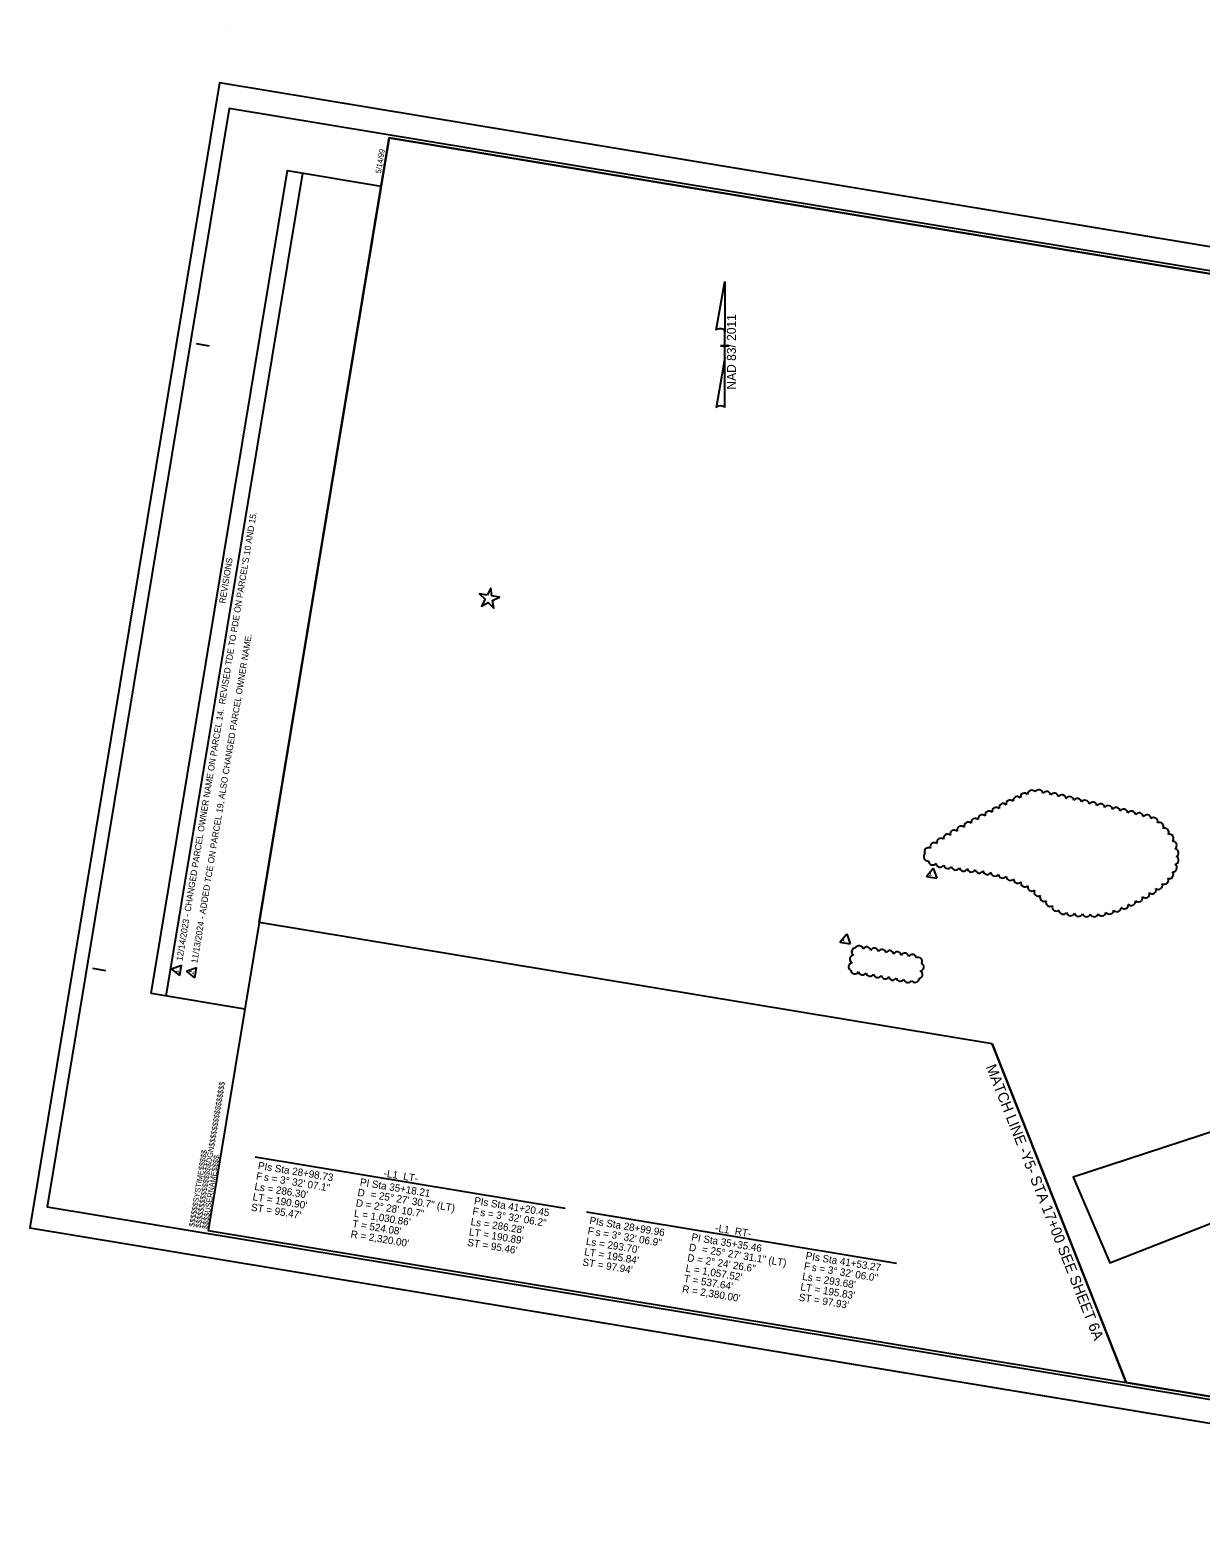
# Model space of a CAD drawing. Extents: x 2191522 to 2193565, y 85992 to 87403.
# Drawn here: x 2191522 to 2192631, y 85992 to 87403 of the extents above; entities that cross this region are included whole.
import ezdxf

# ---------------------------------------------------------------- set-up
doc = ezdxf.new("R2010")
doc.units = 0
for name, color, linetype in [('Exist Roads EOP', 7, 'Continuous'), ('Exist Structure Minor Footbridge', 7, 'Continuous'), ('Model Boundary Lines', 7, 'Continuous'), ('Model Boundary Lines Text', 7, 'Continuous'), ('Old_Level_2', 7, 'Continuous'), ('Scratch_Level_0', 7, 'Continuous'), ('Sheet Border Standard 30in CELL', 7, 'Continuous'), ('Sheet Cutting Line CELL', 7, 'Continuous'), ('Sheet Plot Border Inside CELL', 7, 'Continuous'), ('Sheet Plot Border Outside CELL', 7, 'Continuous')]:
    doc.layers.add(name, color=color, linetype=linetype)

msp = doc.modelspace()

# ---------------------------------------------------------------- linework, layer by layer
at = {"layer": 'Exist Roads EOP'}
for p, q in [((2191651.6, 86487.2), (2191780.9, 87267.2)), ((2192371.8, 86600.5), (2192378.1, 86608.4)), ((2192378.1, 86608.4), (2192381.6, 86598.9)), ((2192371.8, 86600.5), (2192381.6, 86598.9)), ((2192289.7, 86538.3), (2192296.1, 86546.2)), ((2192289.7, 86538.3), (2192299.5, 86536.7)), ((2192296.1, 86546.2), (2192299.5, 86536.7)), ((2191656.5, 86513.1), (2191666, 86516.6)), ((2191664.4, 86506.8), (2191656.5, 86513.1)), ((2191664.4, 86506.8), (2191666, 86516.6)), ((2191670.6, 86510.8), (2191680.1, 86514.3)), ((2191678.5, 86504.5), (2191670.6, 86510.8)), ((2191678.5, 86504.5), (2191680.1, 86514.3))]:
    msp.add_line(p, q, dxfattribs=at)
msp.add_lwpolyline([(2191637.3, 86489.6), (2191766.5, 87269.6), (2191855.1, 87254.9), (2191725.9, 86474.9)], close=True, dxfattribs=at)
for centre, radius, start, end in [((2192464.5, 86675.6), 3.94, 42.184, 187.184), ((2192471.3, 86678.4), 3.94, 37.1203, 182.1203), ((2192477.9, 86678.9), 3.94, 6.4213, 151.4213), ((2192485.3, 86677.3), 3.94, 4.7516, 149.7516), ((2192492.6, 86675.7), 3.94, 4.5876, 149.5876), ((2192499.9, 86674), 3.94, 4.5037, 149.5037), ((2192437.7, 86662.2), 3.94, 45.0572, 190.0572), ((2192444.3, 86665.7), 3.94, 44.7241, 189.7241), ((2192451, 86669.1), 3.94, 44.2581, 189.2581), ((2192457.7, 86672.4), 3.94, 43.5376, 188.5376), ((2192507.2, 86672.3), 3.94, 4.4503, 149.4503), ((2192514.5, 86670.6), 3.94, 4.4124, 149.4124), ((2192521.8, 86668.9), 3.94, 4.3838, 149.3838), ((2192529.2, 86667.2), 3.94, 4.3612, 149.3612), ((2192536.5, 86665.5), 3.94, 4.3514, 149.3514), ((2192543.8, 86663.8), 3.94, 4.3514, 149.3514), ((2192551.1, 86662.1), 3.94, 4.3514, 149.3514), ((2192558.4, 86660.4), 3.94, 4.3514, 149.3514), ((2192411.2, 86648.1), 3.94, 46.3521, 191.3521), ((2192417.8, 86651.7), 3.94, 45.8668, 190.8668), ((2192424.4, 86655.2), 3.94, 45.519, 190.519), ((2192431, 86658.7), 3.94, 45.3108, 190.3108), ((2192565.7, 86658.6), 3.94, 4.3514, 149.3514), ((2192573.1, 86656.9), 3.94, 4.3514, 149.3514), ((2192580.4, 86655.2), 3.94, 4.3514, 149.3514), ((2192586.8, 86652.5), 3.94, 344.3792, 129.3792), ((2192592.4, 86647.9), 3.94, 332.5229, 117.5229), ((2192385.4, 86632.9), 3.94, 50.5072, 195.5072), ((2192391.7, 86636.8), 3.94, 48.8492, 193.8492), ((2192398.1, 86640.7), 3.94, 47.7533, 192.7533), ((2192404.6, 86644.4), 3.94, 46.9602, 191.9602), ((2192597.4, 86642.5), 3.94, 327.8467, 112.8467), ((2192601.7, 86636.6), 3.94, 318.449, 103.449), ((2192372.9, 86619.4), 3.94, 135.4839, 280.4839), ((2192373.6, 86623.9), 3.94, 61.669, 206.669), ((2192379.2, 86628.6), 3.94, 53.4684, 198.4684), ((2192604.8, 86630), 3.94, 308.1648, 93.1648), ((2192606.6, 86623), 3.94, 294.9528, 79.9528), ((2192377.6, 86615.4), 3.94, 178.1556, 323.1556), ((2192384.6, 86613.3), 3.94, 184.4334, 329.4334), ((2192391.9, 86611.9), 3.94, 187.3592, 332.3592), ((2192399.3, 86610.6), 3.94, 189.1365, 334.1365), ((2192406.7, 86609.6), 3.94, 190.3607, 335.3607), ((2192414.2, 86608.7), 3.94, 190.4949, 335.4949), ((2192604.9, 86608.9), 3.94, 267.7815, 52.7815), ((2192606.6, 86615.9), 3.94, 280.1316, 65.1316), ((2192421.7, 86607.7), 3.94, 188.8315, 333.8315), ((2192429.1, 86606.4), 3.94, 186.8467, 331.8467), ((2192436.5, 86604.9), 3.94, 184.5107, 329.5107), ((2192443.8, 86603), 3.94, 181.722, 326.722), ((2192451.1, 86600.7), 3.94, 178.3408, 323.3408), ((2192458.1, 86598), 3.94, 174.1741, 319.1741), ((2192465, 86594.6), 3.94, 168.9629, 313.9629), ((2192591.3, 86592.3), 3.94, 234.6256, 19.6256), ((2192596.9, 86597.1), 3.94, 240.9529, 25.9529), ((2192601.6, 86602.5), 3.94, 252.7106, 37.7106), ((2192471.5, 86590.6), 3.94, 162.3858, 307.3858), ((2192477.5, 86585.9), 3.94, 155.7293, 300.7293), ((2192483.1, 86580.9), 3.94, 156.1791, 301.1791), ((2192572.4, 86580.4), 3.94, 225.8288, 10.8288), ((2192578.9, 86584.1), 3.94, 227.8967, 12.8967), ((2192585.2, 86588), 3.94, 230.6533, 15.6533), ((2192488.8, 86576.1), 3.94, 158.5484, 303.5484), ((2192494.7, 86571.7), 3.94, 163.4577, 308.4577), ((2192501.1, 86568.7), 3.94, 180.9521, 325.9521), ((2192508.2, 86567.3), 3.94, 192.2119, 337.2119), ((2192515.7, 86566.7), 3.94, 193.727, 338.727), ((2192523.2, 86566.3), 3.94, 194.5399, 339.5399), ((2192530.5, 86566.3), 3.94, 200.4618, 345.4618), ((2192537.8, 86567.1), 3.94, 207.9418, 352.9418), ((2192545, 86568.8), 3.94, 213.4956, 358.4956), ((2192552.1, 86571.1), 3.94, 217.7221, 2.7221), ((2192559, 86573.9), 3.94, 221.0291, 6.0291), ((2192565.7, 86577), 3.94, 223.6842, 8.6842), ((2192302.9, 86522.2), 3.82, 98.0917, 243.0917), ((2192304.6, 86529.1), 3.82, 90.4337, 235.4337), ((2192307.9, 86531.2), 3.82, 8.0917, 153.0917), ((2192315.1, 86530), 3.82, 8.0917, 153.0917), ((2192322.3, 86528.8), 3.82, 8.0917, 153.0917), ((2192329.5, 86527.7), 3.82, 8.0917, 153.0917), ((2192336.7, 86526.5), 3.82, 8.0917, 153.0917), ((2192343.9, 86525.3), 3.82, 8.0917, 153.0917), ((2192351.1, 86524.1), 3.82, 8.0917, 153.0917), ((2192358.3, 86522.9), 3.82, 8.0917, 153.0917), ((2192363.7, 86520), 3.82, 330.5198, 115.5198), ((2192301.7, 86515), 3.82, 98.0917, 243.0917), ((2192303.8, 86512.1), 3.82, 188.0917, 333.0917), ((2192311, 86511), 3.82, 188.0917, 333.0917), ((2192318.2, 86509.8), 3.82, 188.0917, 333.0917), ((2192364.1, 86507.5), 3.82, 278.0917, 63.0917), ((2192365.3, 86514.7), 3.82, 278.0917, 63.0917), ((2192325.4, 86508.6), 3.82, 188.0917, 333.0917), ((2192332.6, 86507.4), 3.82, 188.0917, 333.0917), ((2192339.7, 86506.2), 3.82, 188.0917, 333.0917), ((2192346.9, 86505), 3.82, 188.0917, 333.0917), ((2192354.1, 86503.8), 3.82, 188.0917, 333.0917), ((2192360.8, 86504), 3.82, 210.4855, 355.4855)]:
    msp.add_arc(centre, radius, start, end, dxfattribs=at)
at = {"layer": 'Exist Structure Minor Footbridge'}
msp.add_lwpolyline([(2191955.5, 86867.3), (2191948.4, 86868.5), (2191953.5, 86863.3), (2191950.1, 86856.8), (2191956.6, 86860.1), (2191961.7, 86854.9), (2191960.6, 86862.1), (2191967.1, 86865.4), (2191960, 86866.5), (2191958.9, 86873.7), (2191955.5, 86867.3)], dxfattribs=at)
at = {"layer": 'Model Boundary Lines'}
for p, q in [((2192172.4, 87118.3), (2192180.6, 87164.6)), ((2192180.6, 87164.6), (2192180.6, 87164.6)), ((2192180.6, 87164.6), (2192180.6, 87164.6)), ((2192180.6, 87164.6), (2192180.6, 87116.8)), ((2192180.6, 87092), (2192180.6, 87118.2)), ((2192180.6, 87116.8), (2192180.6, 87118.2)), ((2192180.2, 87103.6), (2192176.6, 87103.6)), ((2192176.6, 87103.6), (2192176.6, 87103.6)), ((2192176.7, 87103.6), (2192184.7, 87103.6)), ((2192180.6, 87092), (2192172.3, 87044.8)), ((2192180.7, 87045), (2192180.6, 87092))]:
    msp.add_line(p, q, dxfattribs=at)
for centre, start_param, end_param in [((2192176.5, 87117.8), 0.216388, 2.908219), ((2192176.5, 87044.6), 0.201328, 3.141593)]:
    msp.add_ellipse(centre, major_axis=(4.23, -0.03), ratio=0.461098, start_param=start_param, end_param=end_param, dxfattribs=at)
at = {"layer": 'Model Boundary Lines Text'}
for p, q in [((2191735.6, 86334.8), (2192029.3, 86286.1)), ((2192049.7, 86282.7), (2192343.3, 86234.1))]:
    msp.add_line(p, q, dxfattribs=at)
at = {"layer": 'Old_Level_2'}
msp.add_lwpolyline([(2192434, 86441.8), (2191739.5, 86556.9), (2191853, 87242.1), (2191862.7, 87300.8), (2193012.6, 87110.3), (2193009.4, 87091.1), (2192997.5, 87019.1), (2193130.1, 86997.1), (2193116.8, 86917.1), (2193222.5, 86899.6), (2193235.6, 86410.4), (2193213.8, 86278.1), (2193023.9, 86309.5), (2192994.1, 86129.4), (2192901.4, 86144.8), (2192889.2, 86066.4), (2192560.7, 86120.9), (2192457.9, 86381.3)], close=True, dxfattribs=at)
msp.add_lwpolyline([(2192752, 86394.5), (2192510.7, 86315.5), (2192510.7, 86315.5), (2192545.4, 86234.5), (2192545.4, 86234.5), (2192721.3, 86303.1)], dxfattribs=at)
at = {"layer": 'Scratch_Level_0'}
for p, q in [((2191710.4, 87403.1), (2191710.4, 87403.1)), ((2192434, 86441.8), (2191739.5, 86556.9)), ((2192434, 86441.8), (2192560.7, 86120.9))]:
    msp.add_line(p, q, dxfattribs=at)
at = {"layer": 'Sheet Border Standard 30in CELL'}
for p, q in [((2191863.7, 87300.7), (2191863.7, 87300.7)), ((2191679.9, 87105.6), (2191692.2, 87103.6)), ((2191581.8, 86513.7), (2191594.1, 86511.6))]:
    msp.add_line(p, q, dxfattribs=at)
msp.add_lwpolyline([(2193342.6, 87055.6), (2191862.7, 87300.8), (2191691.1, 86265), (2193170.9, 86019.8)], close=True, dxfattribs=at)
at = {"layer": 'Sheet Cutting Line CELL'}
for p, q in [((2191702.1, 87352.8), (2191522.3, 86267.6)), ((2193363.4, 87077.5), (2191702.1, 87352.8)), ((2191522.3, 86267.6), (2193183.6, 85992.3))]:
    msp.add_line(p, q, dxfattribs=at)
at = {"layer": 'Sheet Plot Border Inside CELL'}
msp.add_lwpolyline([(2193355.3, 87056.1), (2191711.2, 87328.5), (2191538.7, 86287.6), (2193182.8, 86015.2)], close=True, dxfattribs=at)
at = {"layer": 'Sheet Plot Border Outside CELL'}
msp.add_lwpolyline([(2193363.4, 87077.5), (2191702.1, 87352.8), (2191522.3, 86267.6), (2193183.6, 85992.3)], close=True, dxfattribs=at)

# ---------------------------------------------------------------- texts
at = {"layer": 'Exist Roads EOP'}
for s, height, rotation, p in [("  12/14/2023 - CHANGED PARCEL OWNER NAME ON PARCEL 14.  REVISED TDE TO PDE ON PARCEL'S 10 AND 15.", 6, 80.5917, (2191666.1, 86515.8)), ('REVISIONS', 6, 80.5917, (2191707.4, 86859)), ('  11/13/2024 - ADDED TCE ON PARCEL 19, ALSO CHANGED PARCEL OWNER NAME.', 6, 80.5917, (2191680.2, 86513.5)), (' 1', 4.5, 350.5917, (2192371.6, 86601.9)), (' 1', 4.5, 350.5917, (2192289.6, 86539.7)), (' 1', 4.5, 80.5917, (2191663, 86506.6)), ('2', 4.5, 80.5917, (2191677.5, 86507.4))]:
    msp.add_text(s, height=height, rotation=rotation, dxfattribs=at).set_placement(p)
at = {"layer": 'Model Boundary Lines'}
msp.add_text('NAD 83/ 2011', height=8.5, rotation=90, dxfattribs=at).set_placement((2192191.1, 87062.1))
at = {"layer": 'Model Boundary Lines Text'}
for s, rotation, p in [('PIs Sta 28+98.73', 350.5917, (2191738, 86323.4)), ('F', 350.5917, (2191736.3, 86313.5)), ('s = 3%%d 32\' 07.1"', 350.5917, (2191743.7, 86312.3)), ('PI Sta 35+18.21', 350.5917, (2191834.6, 86307.7)), ('-L1_LT-', 350.5915, (2191857.1, 86316.2)), ("LT = 190.90'", 350.5917, (2191733, 86293.8)), ("Ls = 286.30'", 350.5917, (2191734.7, 86303.6)), ('D', 350.5917, (2191832.3, 86297.9)), ('= 25%%d 27\' 30.7" (LT)', 350.5917, (2191844.6, 86296)), ('PIs Sta 41+20.45', 350.5917, (2191942.8, 86290.1)), ("ST = 95.47'", 350.5917, (2191731.4, 86283.9)), ("L = 1,030.86'", 350.5917, (2191829, 86278.2)), ('D = 2%%d 28\' 10.7"', 350.5917, (2191830.7, 86288)), ('F', 350.5917, (2191941.2, 86280.2)), ('s = 3%%d 32\' 06.2"', 350.5917, (2191948.6, 86279)), ("T = 524.08'", 350.5917, (2191827.4, 86268.3)), ("Ls = 286.28'", 350.5917, (2191939.5, 86270.3)), ('PIs Sta 28+99.96', 350.5917, (2192052, 86271.3)), ('-L1_RT-', 350.5915, (2192171.2, 86264.2)), ("R = 2,320.00'", 350.5917, (2191825.8, 86258.4)), ("ST = 95.46'", 350.5917, (2191936.3, 86250.6)), ("LT = 190.89'", 350.5917, (2191937.9, 86260.5)), ("Ls = 293.70'", 350.5917, (2192048.7, 86251.6)), ('F', 350.5917, (2192050.3, 86261.5)), ('s = 3%%d 32\' 06.9"', 350.5917, (2192057.8, 86260.2)), ('PI Sta 35+35.46', 350.5917, (2192148.6, 86255.6)), ("LT = 195.84'", 350.5917, (2192047.1, 86241.7)), ('D = 2%%d 24\' 26.6"', 350.5917, (2192144.7, 86236)), ('D', 350.5917, (2192146.3, 86245.9)), ('= 25%%d 27\' 31.1" (LT)', 350.5917, (2192158.6, 86244)), ('PIs Sta 41+53.27', 350.5917, (2192256.8, 86238)), ("ST = 97.94'", 350.5917, (2192045.4, 86231.9)), ("L = 1,057.52'", 350.5917, (2192143.1, 86226.1)), ('F', 350.5917, (2192255.2, 86228.2)), ('s = 3%%d 32\' 06.0"', 350.5917, (2192262.6, 86226.9)), ("R = 2,380.00'", 350.5917, (2192139.8, 86206.4)), ("T = 537.64'", 350.5917, (2192141.4, 86216.3)), ("LT = 195.83'", 350.5917, (2192251.9, 86208.4)), ("Ls = 293.68'", 350.5917, (2192253.6, 86218.3)), ("ST = 97.93'", 350.5917, (2192250.3, 86198.6))]:
    msp.add_text(s, height=7, rotation=rotation, dxfattribs=at).set_placement(p)
at = {"layer": 'Scratch_Level_0'}
msp.add_text('MATCH LINE -Y5- STA 17+00 SEE SHEET 6A', height=10, rotation=291.5478, dxfattribs=at).set_placement((2192427.8, 86420.2))
at = {"layer": 'Sheet Border Standard 30in CELL'}
for s, p in [('5/14/99', (2191854.8, 87266.5)), ('$$$$$$$$$$$$$$$$DGN$$$$$$$$$$$$$$$$', (2191684.2, 86267)), ('$$$$$$SYSTIME$$$$$', (2191678.2, 86268.2)), ('$$$$USERNAME$$$$', (2191690.4, 86266))]:
    msp.add_text(s, height=5.25, rotation=80.5917, dxfattribs=at).set_placement(p)

doc.saveas('drawing.dxf')
